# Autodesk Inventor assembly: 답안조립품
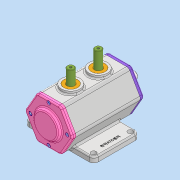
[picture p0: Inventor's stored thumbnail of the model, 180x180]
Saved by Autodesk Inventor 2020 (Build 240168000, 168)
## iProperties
Created: 2021-06
Part Number: 답안조립품
Document SubType Name: Assembly
Designer: MIRAE
Author: MIRAE
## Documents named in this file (11)
- C:\Users\MIRAE\Desktop\710606V1017\답안조립품.iam
- C:\Users\MIRAE\Desktop\710606V1017\본체.ipt
- C:\Users\MIRAE\Desktop\710606V1017\뒷커버.ipt
- C:\Users\MIRAE\Desktop\710606V1017\베어링 6302.ipt
- C:\Users\MIRAE\Desktop\710606V1017\편심축.ipt
- C:\Users\MIRAE\Desktop\710606V1017\슬라이더.ipt
- C:\Users\MIRAE\Desktop\710606V1017\베어링 6203.ipt
- C:\Users\MIRAE\Desktop\710606V1017\앞커버.ipt
- C:\Users\MIRAE\Desktop\710606V1017\볼트 M4.ipt
- C:\Users\MIRAE\Desktop\710606V1017\오일실.ipt
- C:\Users\MIRAE\Desktop\710606V1017\부시.ipt
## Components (10 placed, 3 different names)
1. 7-베어링 6203:1
2. 8-오일실:1
3. 9-M4-소켓머리:1
4. 9-M4-소켓머리:2
5. 9-M4-소켓머리:3
6. 9-M4-소켓머리:4
7. 9-M4-소켓머리:5
8. 9-M4-소켓머리:6
9. 9-M4-소켓머리:7
10. 9-M4-소켓머리:8
